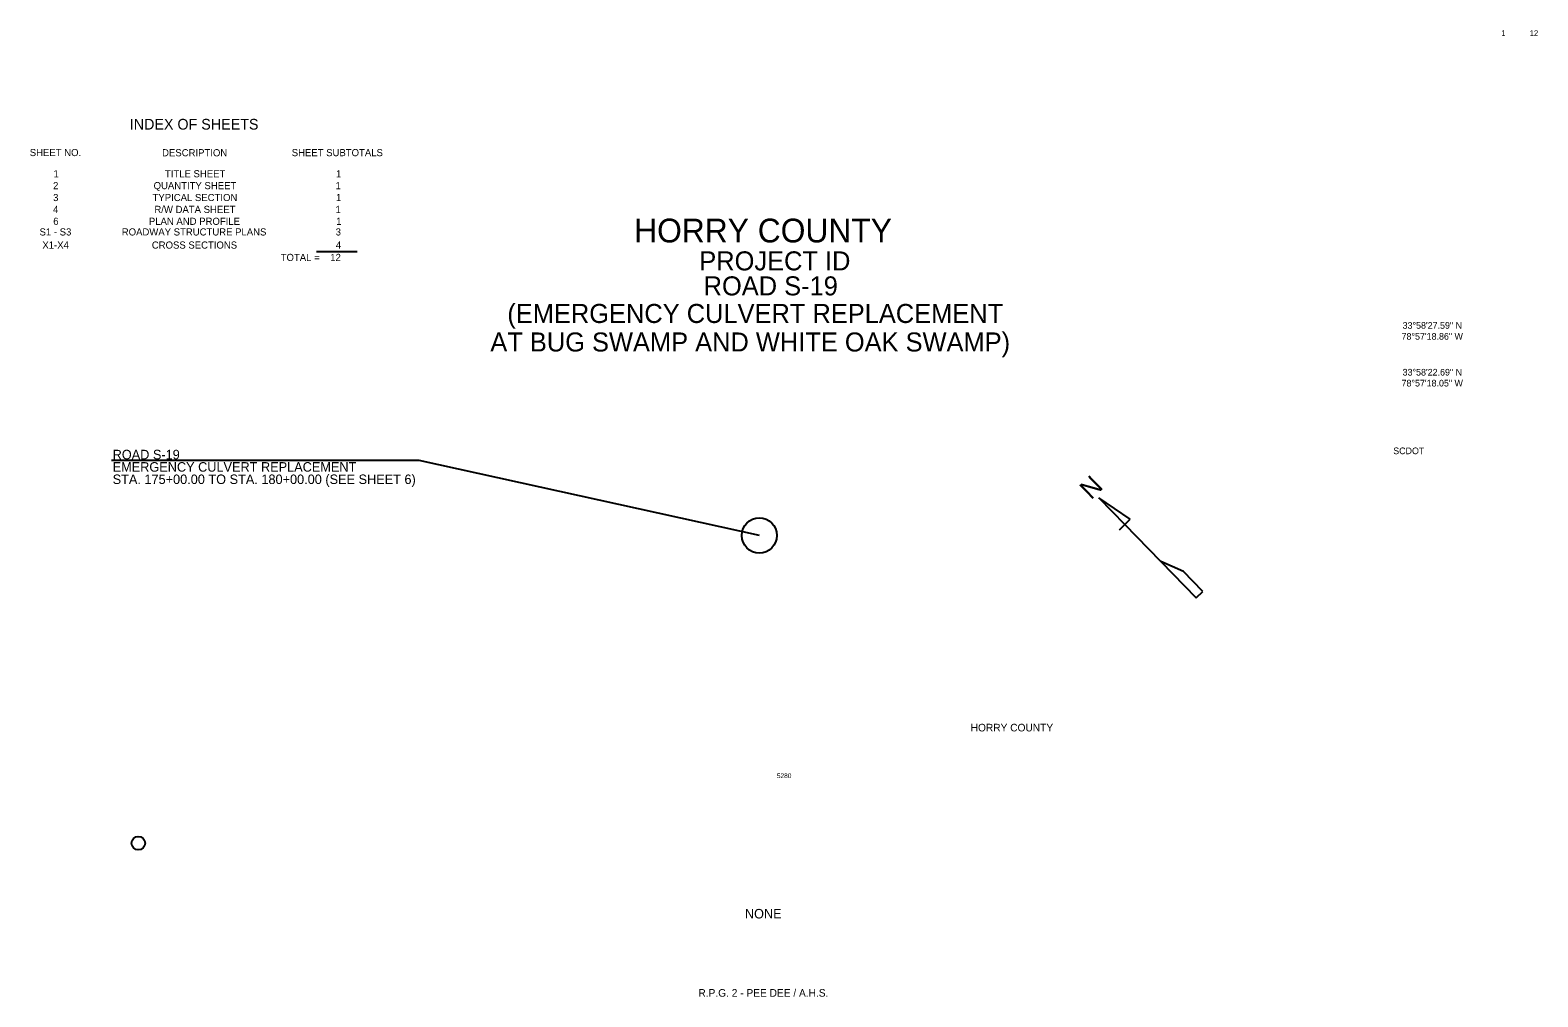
# Model space of a CAD drawing. Extents: x -742 to 844, y 45 to 1061.
import ezdxf

# ---------------------------------------------------------------- set-up
doc = ezdxf.new("R2010")
doc.units = 0
for name, color, linetype in [('Default', 7, 'Continuous'), ('RD_EX_Misc', 7, 'Continuous'), ('RD_Sketch1', 7, 'Continuous'), ('RD_Sketch3', 7, 'Continuous'), ('RD_TX_TitleSht', 7, 'Continuous')]:
    doc.layers.add(name, color=color, linetype=linetype)

# ---------------------------------------------------------------- blocks, each defined once
blk = doc.blocks.new('NA1')
at = {"layer": 'RD_EX_Misc'}
for p, q in [((7.9, 31.1), (0.1, 70.3)), ((0.1, 70.3), (0.1, 70.3)), ((0.1, 70.3), (0.1, 31.1)), ((-7.8, 31.1), (0.1, 31.1)), ((0.1, -23.3), (0.1, 31.1)), ((0.1, 31.1), (7.9, 31.1)), ((7.9, 31.1), (7.9, 31.5)), ((9.9, -47.3), (0.1, -23.3)), ((0.1, -23.3), (0.1, -76.7)), ((9.9, -76.7), (9.9, -47.1)), ((9.9, -47.1), (9.9, -47.3)), ((0.1, -76.7), (9.9, -76.7))]:
    blk.add_line(p, q, dxfattribs=at)
blk.add_text('N', height=20, dxfattribs=at).set_placement((-7.8, 74))

msp = doc.modelspace()

# ---------------------------------------------------------------- linework, layer by layer
at = {"layer": 'Default'}
for p, q in [((-332.9, 608.8), (-656.6, 608.8)), ((25, 529.9), (-332.9, 608.8))]:
    msp.add_line(p, q, dxfattribs=at)
at = {"layer": 'RD_Sketch1'}
msp.add_circle((25, 529.9), 18.5, dxfattribs=at)
at = {"layer": 'RD_Sketch3'}
msp.add_circle((-628.3, 206.3), 7.08, dxfattribs=at)
at = {"layer": 'RD_TX_TitleSht'}
msp.add_line((-440.7, 828.7), (-398, 828.7), dxfattribs=at)

# ---------------------------------------------------------------- block references
at = {"layer": 'Default', "rotation": 44.16600486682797}
msp.add_blockref('NA1', (431.1, 519.1), dxfattribs=at)

# ---------------------------------------------------------------- texts
at = {"layer": 'Default'}
msp.add_text('5280', height=5, dxfattribs=at).set_placement((43.4, 274.7))
at = {"layer": 'RD_TX_TitleSht'}
for s, height, p in [('1', 6, (805.5, 1055.3)), ('12', 6, (835.4, 1055.3)), ('INDEX OF SHEETS', 11.25, (-637.3, 956.8)), ('HORRY COUNTY', 25, (-106.7, 838.1)), (' PROJECT ID ', 20, (-45.6, 808.7)), ('ROAD S-19', 20, (-33.6, 782.4)), ('(EMERGENCY CULVERT REPLACEMENT', 20, (-240.1, 753.4)), ('33°58\'27.59" N', 7, (701.7, 747.3)), ('AT BUG SWAMP AND WHITE OAK SWAMP)', 20, (-258, 723.4)), ('78°57\'18.86" W', 7, (700.6, 735.8)), ('33°58\'22.69" N', 7, (701.7, 698.1)), ('78°57\'18.05" W', 7, (700.6, 686.6)), ('ROAD S-19 ', 10, (-655.3, 610)), ('SCDOT', 7, (691.8, 615.4)), ('EMERGENCY CULVERT REPLACEMENT', 10, (-655.3, 597)), ('STA. 175+00.00 TO STA. 180+00.00 (SEE SHEET 6)', 10, (-655.3, 584)), ('HORRY COUNTY', 8, (247.3, 323.8)), ('NONE', 10, (9.8, 127.1)), ('R.P.G. 2 - PEE DEE / A.H.S.', 8, (-39.1, 44.8))]:
    msp.add_text(s, height=height, dxfattribs=at).set_placement(p)
for s, p in [('SHEET NO.', (-742.5, 928.9)), ('DESCRIPTION', (-603.3, 928.7)), ('SHEET SUBTOTALS', (-466.9, 928.8)), ('1', (-717.5, 906.6)), ('TITLE SHEET', (-600.3, 906.6)), ('1', (-420.4, 906.6)), ('2', (-718, 894.1)), ('3', (-717.9, 881.6)), ('TYPICAL SECTION', (-613.3, 881.6)), ('QUANTITY SHEET', (-612.2, 894.1)), ('1', (-420.8, 894.1)), ('1', (-420.4, 881.6)), ('4', (-718, 869.1)), ('R/W DATA SHEET', (-611.4, 869.1)), ('1', (-420.8, 869.1)), ('6', (-717.8, 856.6)), ('PLAN AND PROFILE', (-617.2, 856.6)), ('1', (-420.2, 856.6)), ('S1 - S3', (-732.2, 845.4)), ('ROADWAY STRUCTURE PLANS', (-645.7, 845.4)), ('3', (-420.7, 845.4)), ('X1-X4', (-729.2, 831.6)), ('CROSS SECTIONS', (-614.1, 831.6)), ('TOTAL =    12', (-478.5, 818.6)), ('4', (-420.5, 831.6))]:
    msp.add_text(s, height=7.5, rotation=360, dxfattribs=at).set_placement(p)

doc.saveas('drawing.dxf')
